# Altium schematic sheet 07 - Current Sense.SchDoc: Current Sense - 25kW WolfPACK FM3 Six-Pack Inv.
size 431 x 279 mm; Date: 01/2024; DocumentNumber: CRD25DA12N-FMC; Revision: 1.2; SheetNumber: 7; SheetTotal: 8; SheetSize: B
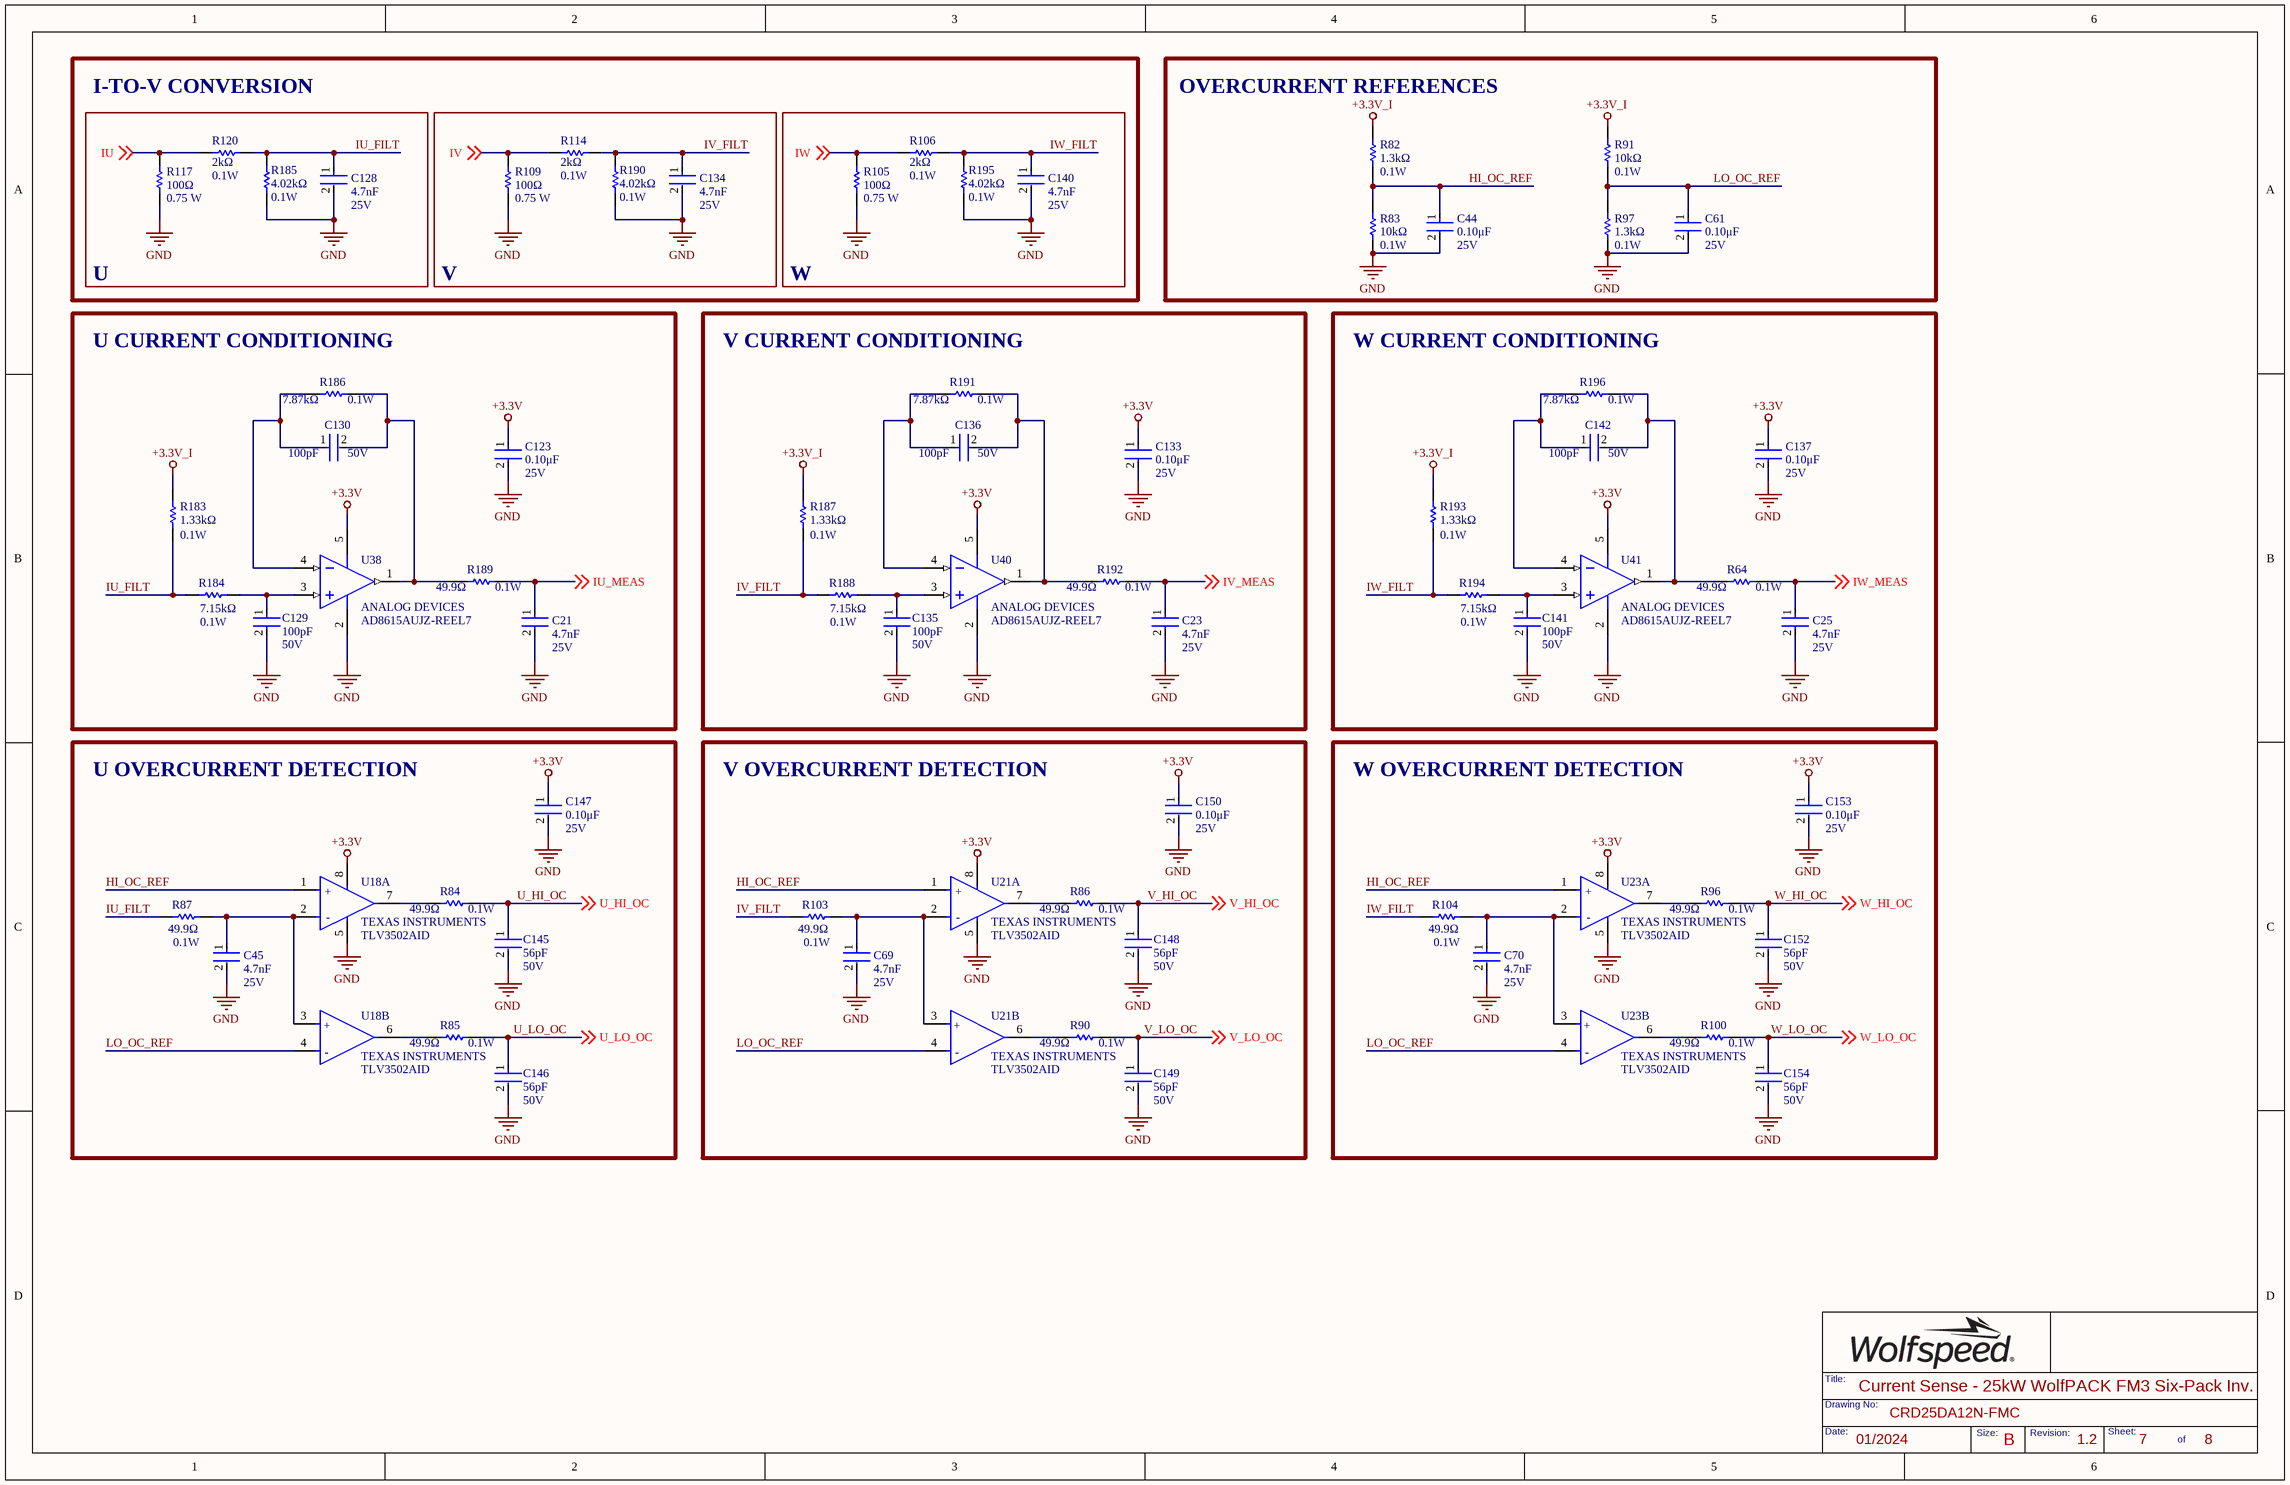
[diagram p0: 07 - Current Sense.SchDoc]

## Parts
C21  Voltage Rating: 25V  Capacitance: 4.7nF  [FP-C0603C-CF-IPC_B]  (hidden comment: C0603C472K3RAC7867)
C23  Voltage Rating: 25V  Capacitance: 4.7nF  [FP-C0603C-CF-IPC_B]  (hidden comment: C0603C472K3RAC7867)
C25  Voltage Rating: 25V  Capacitance: 4.7nF  [FP-C0603C-CF-IPC_B]  (hidden comment: C0603C472K3RAC7867)
C44  Voltage Rating: 25V  Capacitance: 0.10μF  [FP-C0603C-CF-IPC_B]  (hidden comment: C0603C104K3RACTU)
C45  Voltage Rating: 25V  Capacitance: 4.7nF  [FP-C0603C-CF-IPC_B]  (hidden comment: C0603C472K3RAC7867)
C61  Voltage Rating: 25V  Capacitance: 0.10μF  [FP-C0603C-CF-IPC_B]  (hidden comment: C0603C104K3RACTU)
C69  Voltage Rating: 25V  Capacitance: 4.7nF  [FP-C0603C-CF-IPC_B]  (hidden comment: C0603C472K3RAC7867)
C70  Voltage Rating: 25V  Capacitance: 4.7nF  [FP-C0603C-CF-IPC_B]  (hidden comment: C0603C472K3RAC7867)
C123  Voltage Rating: 25V  Capacitance: 0.10μF  [FP-C0603C-CF-IPC_B]  (hidden comment: C0603C104K3RACTU)
C128  Voltage Rating: 25V  Capacitance: 4.7nF  [FP-C0603C-CF-IPC_B]  (hidden comment: C0603C472K3RAC7867)
C129  Capacitance: 100pF  Voltage: 50V  [FP-C0603C-CF-IPC_B]  (hidden comment: CL10C101JB8NNNC)
C130  Capacitance: 100pF  Voltage: 50V  [FP-C0603C-CF-IPC_B]  (hidden comment: CL10C101JB8NNNC)
C133  Voltage Rating: 25V  Capacitance: 0.10μF  [FP-C0603C-CF-IPC_B]  (hidden comment: C0603C104K3RACTU)
C134  Voltage Rating: 25V  Capacitance: 4.7nF  [FP-C0603C-CF-IPC_B]  (hidden comment: C0603C472K3RAC7867)
C135  Capacitance: 100pF  Voltage: 50V  [FP-C0603C-CF-IPC_B]  (hidden comment: CL10C101JB8NNNC)
C136  Capacitance: 100pF  Voltage: 50V  [FP-C0603C-CF-IPC_B]  (hidden comment: CL10C101JB8NNNC)
C137  Voltage Rating: 25V  Capacitance: 0.10μF  [FP-C0603C-CF-IPC_B]  (hidden comment: C0603C104K3RACTU)
C140  Voltage Rating: 25V  Capacitance: 4.7nF  [FP-C0603C-CF-IPC_B]  (hidden comment: C0603C472K3RAC7867)
C141  Capacitance: 100pF  Voltage: 50V  [FP-C0603C-CF-IPC_B]  (hidden comment: CL10C101JB8NNNC)
C142  Capacitance: 100pF  Voltage: 50V  [FP-C0603C-CF-IPC_B]  (hidden comment: CL10C101JB8NNNC)
C145  Capacitance: 56pF  Voltage Rating: 50V  [FP-C0603C-CF-IPC_B]  (hidden comment: CL10C560JB8NNNC)
C146  Capacitance: 56pF  Voltage Rating: 50V  [FP-C0603C-CF-IPC_B]  (hidden comment: CL10C560JB8NNNC)
C147  Voltage Rating: 25V  Capacitance: 0.10μF  [FP-C0603C-CF-IPC_B]  (hidden comment: C0603C104K3RACTU)
C148  Capacitance: 56pF  Voltage Rating: 50V  [FP-C0603C-CF-IPC_B]  (hidden comment: CL10C560JB8NNNC)
C149  Capacitance: 56pF  Voltage Rating: 50V  [FP-C0603C-CF-IPC_B]  (hidden comment: CL10C560JB8NNNC)
C150  Voltage Rating: 25V  Capacitance: 0.10μF  [FP-C0603C-CF-IPC_B]  (hidden comment: C0603C104K3RACTU)
C152  Capacitance: 56pF  Voltage Rating: 50V  [FP-C0603C-CF-IPC_B]  (hidden comment: CL10C560JB8NNNC)
C153  Voltage Rating: 25V  Capacitance: 0.10μF  [FP-C0603C-CF-IPC_B]  (hidden comment: C0603C104K3RACTU)
C154  Capacitance: 56pF  Voltage Rating: 50V  [FP-C0603C-CF-IPC_B]  (hidden comment: CL10C560JB8NNNC)
R64  Resistance: 49.9Ω  Power Rating: 0.1W  [FP-MCR03-IPC_B]  (hidden comment: ERJ-3EKF49R9V)
R82  Power Rating: 0.1W  Resistance: 1.3kΩ  [FP-MCR03-IPC_B]  (hidden comment: ERA3AEB132V)
R83  Resistance: 10kΩ  Max Power Dissipation: 0.1W  [FP-MCR03-IPC_B]  (hidden comment: ERJ3EKF1002V)
R84  Resistance: 49.9Ω  Power Rating: 0.1W  [FP-MCR03-IPC_B]  (hidden comment: ERJ-3EKF49R9V)
R85  Resistance: 49.9Ω  Power Rating: 0.1W  [FP-MCR03-IPC_B]  (hidden comment: ERJ-3EKF49R9V)
R86  Resistance: 49.9Ω  Power Rating: 0.1W  [FP-MCR03-IPC_B]  (hidden comment: ERJ-3EKF49R9V)
R87  Resistance: 49.9Ω  Power Rating: 0.1W  [FP-MCR03-IPC_B]  (hidden comment: ERJ-3EKF49R9V)
R90  Resistance: 49.9Ω  Power Rating: 0.1W  [FP-MCR03-IPC_B]  (hidden comment: ERJ-3EKF49R9V)
R91  Resistance: 10kΩ  Max Power Dissipation: 0.1W  [FP-MCR03-IPC_B]  (hidden comment: ERJ3EKF1002V)
R96  Resistance: 49.9Ω  Power Rating: 0.1W  [FP-MCR03-IPC_B]  (hidden comment: ERJ-3EKF49R9V)
R97  Power Rating: 0.1W  Resistance: 1.3kΩ  [FP-MCR03-IPC_B]  (hidden comment: ERA3AEB132V)
R100  Resistance: 49.9Ω  Power Rating: 0.1W  [FP-MCR03-IPC_B]  (hidden comment: ERJ-3EKF49R9V)
R103  Resistance: 49.9Ω  Power Rating: 0.1W  [FP-MCR03-IPC_B]  (hidden comment: ERJ-3EKF49R9V)
R104  Resistance: 49.9Ω  Power Rating: 0.1W  [FP-MCR03-IPC_B]  (hidden comment: ERJ-3EKF49R9V)
R105  value 100Ω  Power: 0.75 W  [RESC2010(5025)_N]  (hidden comment: RC2010FK-07100RL)
R106  Resistance: 2kΩ  Power Rating: 0.1W  [FP-MCR03-IPC_B]  (hidden comment: RT0603DRE072KL)
R109  value 100Ω  Power: 0.75 W  [RESC2010(5025)_N]  (hidden comment: RC2010FK-07100RL)
R114  Resistance: 2kΩ  Power Rating: 0.1W  [FP-MCR03-IPC_B]  (hidden comment: RT0603DRE072KL)
R117  value 100Ω  Power: 0.75 W  [RESC2010(5025)_N]  (hidden comment: RC2010FK-07100RL)
R120  Resistance: 2kΩ  Power Rating: 0.1W  [FP-MCR03-IPC_B]  (hidden comment: RT0603DRE072KL)
R183  Power Rating: 0.1W  Resistance: 1.33kΩ  [FP-MCR03-IPC_B]  (hidden comment: RMCF0603FT1K33)
R184  Resistance: 7.15kΩ  Power Rating: 0.1W  [FP-MCR03-IPC_B]  (hidden comment: RMCF0603FT7K15)
R185  Resistance: 4.02kΩ  Power Rating: 0.1W  [FP-MCR03-IPC_B]  (hidden comment: ERA3AEB4021V)
R186  Resistance: 7.87kΩ  Max Power Dissipation: 0.1W  [FP-MCR03-IPC_B]  (hidden comment: RC0603FR-077K87L)
R187  Power Rating: 0.1W  Resistance: 1.33kΩ  [FP-MCR03-IPC_B]  (hidden comment: RMCF0603FT1K33)
R188  Resistance: 7.15kΩ  Power Rating: 0.1W  [FP-MCR03-IPC_B]  (hidden comment: RMCF0603FT7K15)
R189  Resistance: 49.9Ω  Power Rating: 0.1W  [FP-MCR03-IPC_B]  (hidden comment: ERJ-3EKF49R9V)
R190  Resistance: 4.02kΩ  Power Rating: 0.1W  [FP-MCR03-IPC_B]  (hidden comment: ERA3AEB4021V)
R191  Resistance: 7.87kΩ  Max Power Dissipation: 0.1W  [FP-MCR03-IPC_B]  (hidden comment: RC0603FR-077K87L)
R192  Resistance: 49.9Ω  Power Rating: 0.1W  [FP-MCR03-IPC_B]  (hidden comment: ERJ-3EKF49R9V)
R193  Power Rating: 0.1W  Resistance: 1.33kΩ  [FP-MCR03-IPC_B]  (hidden comment: RMCF0603FT1K33)
R194  Resistance: 7.15kΩ  Power Rating: 0.1W  [FP-MCR03-IPC_B]  (hidden comment: RMCF0603FT7K15)
R195  Resistance: 4.02kΩ  Power Rating: 0.1W  [FP-MCR03-IPC_B]  (hidden comment: ERA3AEB4021V)
R196  Resistance: 7.87kΩ  Max Power Dissipation: 0.1W  [FP-MCR03-IPC_B]  (hidden comment: RC0603FR-077K87L)
U18  TLV3502AID  Manufacturer Print: TEXAS INSTRUMENTS  [FP-D0008A-IPC_B]  (parts A,B of 2)
U21  TLV3502AID  Manufacturer Print: TEXAS INSTRUMENTS  [FP-D0008A-IPC_B]  (parts A,B of 2)
U23  TLV3502AID  Manufacturer Print: TEXAS INSTRUMENTS  [FP-D0008A-IPC_B]  (parts A,B of 2)
U38  Manufacturer: ANALOG DEVICES  [ADI-UJ-5_M]  (hidden comment: AD8615AUJZ-REEL7)
U40  Manufacturer: ANALOG DEVICES  [ADI-UJ-5_M]  (hidden comment: AD8615AUJZ-REEL7)
U41  Manufacturer: ANALOG DEVICES  [ADI-UJ-5_M]  (hidden comment: AD8615AUJZ-REEL7)

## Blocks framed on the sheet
V: C134 R109 R114 R190
W: C140 R105 R106 R195
OVERCURRENT REFERENCES: C44 C61 R82 R83 R91 R97
U CURRENT CONDITIONING: C21 C123 C129 C130 R183 R184 R186 R189 U38
V CURRENT CONDITIONING: C23 C133 C135 C136 R187 R188 R191 R192 U40
W CURRENT CONDITIONING: C25 C137 C141 C142 R64 R193 R194 R196 U41
U OVERCURRENT DETECTION: C45 C145-C147 R84 R85 R87 U18
V OVERCURRENT DETECTION: C69 C148-C150 R86 R90 R103 U21
W OVERCURRENT DETECTION: C70 C152-C154 R96 R100 R104 U23

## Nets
+3.3V: C123.1 C133.1 C137.1 C147.1 C150.1 C153.1 U18.8(V+) U21.8(V+) U23.8(V+) U38.5(+V) U40.5(+V) U41.5(+V)
+3.3V_I: R82.2 R91.2 R183.2 R187.2 R193.2
GND: C21.2 C23.2 C25.2 C44.2 C45.2 C61.2 C69.2 C70.2 C123.2 C128.2 C129.2 C133.2 C134.2 C135.2 C137.2 C140.2 C141.2 C145.2 C146.2 C147.2 C148.2 C149.2 C150.2 C152.2 C153.2 C154.2 R83.1 R97.1 R105.1 R109.1 R117.1 R185.1 R190.1 R195.1 U18.5(V-) U21.5(V-) U23.5(V-) U38.2(-V) U40.2(-V) U41.2(-V)
HI_OC_REF: C44.1 R82.1 R83.2 U18.1(+IN_A) U21.1(+IN_A) U23.1(+IN_A)
IU: R117.2 R120.1 ; off-sheet IU
IU_FILT: C128.1 R87.1 R120.2 R183.1 R184.1 R185.2
IU_MEAS: C21.1 R189.2 ; off-sheet IU_MEAS
IV: R109.2 R114.1 ; off-sheet IV
IV_FILT: C134.1 R103.1 R114.2 R187.1 R188.1 R190.2
IV_MEAS: C23.1 R192.2 ; off-sheet IV_MEAS
IW: R105.2 R106.1 ; off-sheet IW
IW_FILT: C140.1 R104.1 R106.2 R193.1 R194.1 R195.2
IW_MEAS: C25.1 R64.2 ; off-sheet IW_MEAS
LO_OC_REF: C61.1 R91.1 R97.2 U18.4(-IN_B) U21.4(-IN_B) U23.4(-IN_B)
U_HI_OC: C145.1 R84.2 ; off-sheet U_HI_OC
U_LO_OC: C146.1 R85.2 ; off-sheet U_LO_OC
V_HI_OC: C148.1 R86.2 ; off-sheet V_HI_OC
V_LO_OC: C149.1 R90.2 ; off-sheet V_LO_OC
W_HI_OC: C152.1 R96.2 ; off-sheet W_HI_OC
W_LO_OC: C154.1 R100.2 ; off-sheet W_LO_OC
NetC45_1: C45.1 R87.2 U18.2(-IN_A) U18.3(+IN_B)
NetC69_1: C69.1 R103.2 U21.2(-IN_A) U21.3(+IN_B)
NetC70_1: C70.1 R104.2 U23.2(-IN_A) U23.3(+IN_B)
NetC129_1: C129.1 R184.2 U38.3(+IN)
NetC130_1: C130.1 R186.1 U38.4(-IN)
NetC130_2: C130.2 R186.2 R189.1 U38.1(OUT)
NetC135_1: C135.1 R188.2 U40.3(+IN)
NetC136_1: C136.1 R191.1 U40.4(-IN)
NetC136_2: C136.2 R191.2 R192.1 U40.1(OUT)
NetC141_1: C141.1 R194.2 U41.3(+IN)
NetC142_1: C142.1 R196.1 U41.4(-IN)
NetC142_2: C142.2 R64.1 R196.2 U41.1(OUT)
NetR84_1: R84.1 U18.7(OUT_A)
NetR85_1: R85.1 U18.6(OUT_B)
NetR86_1: R86.1 U21.7(OUT_A)
NetR90_1: R90.1 U21.6(OUT_B)
NetR96_1: R96.1 U23.7(OUT_A)
NetR100_1: R100.1 U23.6(OUT_B)

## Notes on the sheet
- I-TO-V CONVERSION
- U

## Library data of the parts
C21 C23 C25 C45 C69 C70 C128 C134 C140 = C0603C472K3RAC7867: CAP CER 4700PF 25V 10% X7R 0603; Manufacturer: KEMET; Manufacturer Part Number: C0603C472K3RACTU; Dielectric Material: Ceramic; Value: 4.7nF
C44 C61 C123 C133 C137 C147 C150 C153 = CMP-2006-03057-2: CAP CER 0.1UF 25V X7R 0603; Manufacturer: KEMET; Value: 0.10μF; Material: Ceramic; Tolerance: 0.1; Temperature Coefficient: 30ppm/°C; Automotive Grade: Grade 1
C129 C130 C135 C136 C141 C142 = CL10C101JB8NNNC: CAP CER 100PF 50V C0G/NP0 0603; Manufacturer: SAMSUNG; Material: Ceramic; Tolerance: 5%; Dielectric: C0G; Temperature Coefficient: 300ppm/°C
C145 C146 C148 C149 C152 C154 = CL10C560JB8NNNC: CAP CER 56PF 50V C0G/NP0 0603; Manufacturer: SAMSUNG; Material: Ceramic; Tolerance: 5%; Dielectric: C0G; Temperature Coefficient: 30ppm/°C
R64 R84-R87 R90 R96 R100 R103 R104 R189 R192 = ERJ-3EKF49R9V: RES SMD 49.9 OHM 1% 1/10W 0603; Manufacturer: PANASONIC; Temperature Coefficient: 100ppm/°C; Voltage Rating: 75V; Max Power Dissipation: 100mW; Voltage Rating (DC): 50V; Working Voltage: 6V; Value: 49.9Ω
R82 R97 = ERA3AEB132V: RES SMD 1.3K OHM 0.1% 1/10W 0603; Manufacturer: PANASONIC; Manufacturer Part Number: ERA-3AEB132V; Temperature Coefficient: 25ppm/°C; Voltage Rating: 75V; Max Power Dissipation: 100mW; Value: 1.3kΩ
R83 R91 = ERJ3EKF1002V: RES SMD 10K OHM 1% 1/10W 0603; Manufacturer: PANASONIC; Manufacturer Part Number: ERJ-3EKF1002V; Temperature Coefficient: 100ppm/°C; Power Rating: 100mW; Voltage Rating: 75V; Value: 10kΩ
R105 R109 R117 = CMP-1017-00397-1: RES 100 OHM 1% 3/4W 2010; Manufacturer: YAGEO; Case-Metric: 5025
R106 R114 R120 = RT0603DRE072KL: RES SMD 2K OHM 0.5% 1/10W 0603; Manufacturer: YAGEO; Temperature Coefficient: 50ppm/°C; Voltage Rating: 75V; Max Power Dissipation: 100mW; Voltage Rating (DC): 50V; Value: 2kΩ
R183 R187 R193 = RMCF0603FT1K33: RES 1.33K OHM 1% 1/10W 0603; Manufacturer: STACKPOLE; Max Power Dissipation: 100mW; Temperature Coefficient: 100ppm/°C; Value: 1.33kΩ
R184 R188 R194 = RMCF0603FT7K15: RES 7.15K OHM 1% 1/10W 0603; Manufacturer: STACKPOLE; Max Power Dissipation: 100mW; Temperature Coefficient: 100ppm/°C; Value: 7.15kΩ
R185 R190 R195 = ERA3AEB4021V: RES SMD 4.02KOHM 0.1% 1/10W 0603; Manufacturer: PANASONIC; Manufacturer Part Number: ERA-3AEB4021V; Voltage Rating: 75V; Temperature Coefficient: 25ppm/°C; Max Power Dissipation: 100mW; Value: 4.02kΩ
R186 R191 R196 = RC0603FR-077K87L: RES 7.87K OHM 1% 1/10W 0603; Manufacturer: YAGEO; Power Rating: 100mW; Temperature Coefficient: 100ppm/°C; Voltage Rating: 50V; Value: 7.87kΩ
U18 U21 U23 = CMP-04896-000023-1: IC COMPARATOR R-R HI-SPD 8-SOIC; Nominal Supply Current: 3.2mA; Standoff Height: 0.11mm; Max Supply Voltage: 5.5V; Min Supply Voltage: 2.2V; Input Bias Current: 0.000002uA; Number Of Channels: 2; Max Junction Temp: +150°C; Input Offset Voltage: 1mV
U38 U40 U41 = CMP-0384-02059-2: IC OPAMP GP 1 CIRCUIT TSOT23-5; Generic Part Number: AD8615; Iq/Amp: 1.7mA; V Span Max: 6V; Amplifiers Per Package: 1; Small Signal Bandwidth: 23MHz; Input Offset Voltage: 80uV; V Span Min: 2.7V; Slew Rate: 12V/us; Input Bias Current: 200fA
